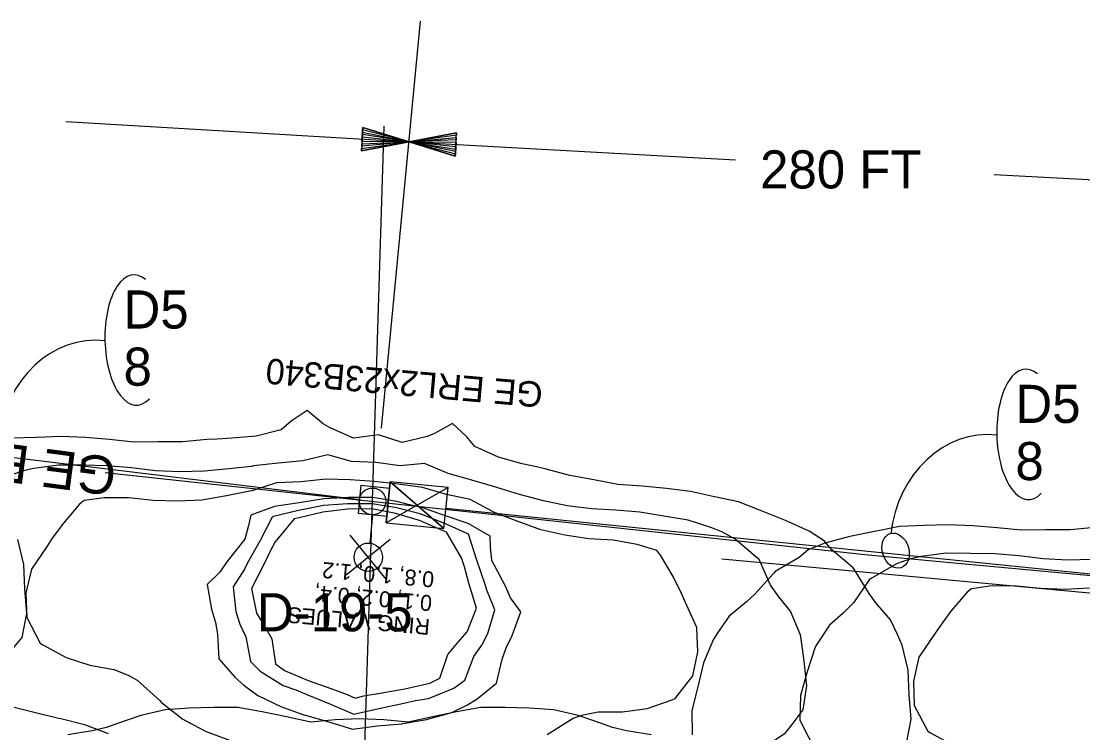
# Model space of a CAD drawing. Extents: x 1638506 to 1658005, y 834807 to 846788.
# Drawn here: x 1642635.4 to 1642969.6, y 842261.9 to 842485.9 of the extents above; entities that cross this region are included whole.
import ezdxf

# ---------------------------------------------------------------- set-up
doc = ezdxf.new("R2010")
doc.units = 0
for name, color, linetype in [('Default', 7, 'Continuous'), ('Exist Guardrail', 7, 'Continuous'), ('Old_Level_1', 7, 'Continuous'), ('Old_Level_2', 7, 'Continuous'), ('Scratch_Level_0', 7, 'Continuous')]:
    doc.layers.add(name, color=color, linetype=linetype)

msp = doc.modelspace()

# ---------------------------------------------------------------- linework, layer by layer
at = {"layer": 'Default'}
for p, q in [((1642756.42, 842436.54), (1642761.14, 842485.89)), ((1642649.53, 842454.33), (1642757.5, 842447.89)), ((1642757.5, 842447.89), (1642860.27, 842442.22)), ((1642941.72, 842437.69), (1643037.67, 842432.39)), ((1642748.87, 842357.77), (1642756.41, 842436.53)), ((1642490.3, 842365.77), (1642742.03, 842335.36)), ((1642768.48, 842326.18), (1642751.59, 842340.91)), ((1642769.78, 842339.08), (1642750.29, 842328.02)), ((1642746.04, 842330.48), (1642745.14, 842321.58)), ((1642769.13, 842332.63), (1643003.18, 842308.79)), ((1642750.36, 842310.22), (1642739.03, 842324.06)), ((1642751.6, 842322.79), (1642737.76, 842311.49)), ((1642744.69, 842317.13), (1642744.69, 842317.13)), ((1642748.18, 842320), (1642748.18, 842320))]:
    msp.add_line(p, q, dxfattribs=at)
for points in [[(1642742.73, 842448.77), (1642742.78, 842449.51), (1642757.5, 842447.89), (1642742.82, 842450.2), (1642742.86, 842450.93), (1642757.5, 842447.89), (1642742.91, 842451.67), (1642742.95, 842452.41), (1642757.5, 842447.89), (1642742.56, 842445.07), (1642742.56, 842445.81), (1642757.5, 842447.89), (1642742.65, 842446.55), (1642742.64, 842447.29), (1642757.5, 842447.89), (1642742.69, 842448.03), (1642742.95, 842452.41), (1642742.56, 842445.07), (1642757.5, 842447.89), (1642742.95, 842452.41)], [(1642772.28, 842447.07), (1642772.24, 842446.33), (1642757.5, 842447.89), (1642772.2, 842445.64), (1642772.16, 842444.91), (1642757.5, 842447.89), (1642772.12, 842444.17), (1642772.08, 842443.43), (1642757.5, 842447.89), (1642772.43, 842450.77), (1642772.44, 842450.03), (1642757.5, 842447.89), (1642772.35, 842449.29), (1642772.36, 842448.55), (1642757.5, 842447.89), (1642772.32, 842447.81), (1642772.08, 842443.43), (1642772.43, 842450.77), (1642757.5, 842447.89), (1642772.08, 842443.43)]]:
    msp.add_lwpolyline(points, dxfattribs=at)
for points in [[(1642769.78, 842339.08), (1642751.59, 842340.91), (1642750.29, 842328.02), (1642768.48, 842326.18)], [(1642760.03, 842333.55), (1642750.29, 842328.02), (1642751.59, 842340.91)], [(1642751.38, 842338.9), (1642750.49, 842330.03), (1642741.59, 842330.93), (1642742.48, 842339.8)], [(1642760.03, 842333.55), (1642768.48, 842326.18), (1642769.78, 842339.08)]]:
    msp.add_lwpolyline(points, close=True, dxfattribs=at)
msp.add_circle((1642744.69, 842317.16), 4.47, dxfattribs=at)
for centre, major_axis, ratio, start_param, end_param in [((1642671.35, 842385.55), (-0.49, 20.52), 0.466223, 5.884886, 7.853982), ((1642658, 842350.99), (-3.78, -34.34), 0.862742, 3.141593, 4.712389), ((1642671.35, 842385.55), (-0.49, 20.52), 0.466223, 1.570796, 3.572354), ((1642952.09, 842355.84), (-0.49, 20.52), 0.466223, 5.884886, 7.853982), ((1642938.74, 842321.27), (-3.78, -34.34), 0.862742, 3.141593, 4.712389), ((1642952.09, 842355.84), (-0.49, 20.52), 0.466223, 1.570796, 3.572354)]:
    msp.add_ellipse(centre, major_axis=major_axis, ratio=ratio, start_param=start_param, end_param=end_param, dxfattribs=at)
msp.add_ellipse((1642910.68, 842319.24), major_axis=(1.72, -5.4), ratio=0.730797, dxfattribs=at)
at = {"layer": 'Exist Guardrail'}
msp.add_lwpolyline([(1642855.97, 842316.64), (1642901.48, 842312.43), (1642956.93, 842307.27), (1643008.14, 842302.6), (1643057.7, 842298.05), (1643110.69, 842293.31), (1643169.76, 842287.95), (1643218.45, 842283.37)], dxfattribs=at)
at = {"layer": 'Old_Level_1'}
for points in [[(1642914.13, 842258.59), (1642915.53, 842266.15), (1642914.97, 842273.87), (1642914.58, 842281.59), (1642912.75, 842289.43), (1642911.29, 842292.79), (1642909.08, 842297.43), (1642904.49, 842302.83), (1642902.38, 842305.69), (1642897.71, 842313.14), (1642897.26, 842313.82), (1642890.59, 842319.52), (1642888.21, 842322.29), (1642883.42, 842325.35), (1642876.04, 842328.71), (1642868.67, 842331.68), (1642868.62, 842331.7), (1642861.19, 842334.59), (1642853.66, 842336.22), (1642846.12, 842337.8), (1642838.53, 842338.8), (1642830.91, 842339.51), (1642823.27, 842340.03), (1642815.73, 842341.53), (1642808.16, 842342.85), (1642800.66, 842344.91), (1642797.58, 842345.58), (1642793.13, 842346.61), (1642785.63, 842348.65), (1642778.24, 842351.97), (1642775.62, 842355.18), (1642771.21, 842359.3), (1642765.57, 842356.06), (1642763.17, 842355.2), (1642755.32, 842353.29), (1642747.85, 842355.64), (1642740.08, 842354.62), (1642732.68, 842357.87), (1642730.46, 842359.13), (1642725.48, 842363.3), (1642720.41, 842360.01), (1642717.28, 842357.3), (1642709.42, 842355.32), (1642701.68, 842354.61), (1642697.12, 842354.37), (1642693.97, 842354.25), (1642686.23, 842353.52), (1642678.55, 842353.53), (1642670.86, 842353.37), (1642663.25, 842354.18), (1642655.62, 842354.8), (1642647.97, 842355.14), (1642640.27, 842354.88), (1642632.57, 842354.59)], [(1642869.82, 842257.66), (1642876.02, 842261.92), (1642878.1, 842264.48), (1642881.53, 842269.12), (1642882.68, 842276.7), (1642881.91, 842284.45), (1642880.87, 842292.22), (1642880.59, 842292.95), (1642877.53, 842300.19), (1642873.93, 842304.65), (1642871.27, 842308.41), (1642867.75, 842316.4), (1642867.32, 842316.8), (1642860.17, 842322.82), (1642856.02, 842325.11), (1642852.8, 842326.41), (1642845.33, 842328.78), (1642837.76, 842330.09), (1642830.19, 842331.31), (1642822.57, 842331.98), (1642814.92, 842332.36), (1642807.33, 842333.33), (1642799.79, 842334.87), (1642792.29, 842336.95), (1642785.49, 842338.96), (1642784.81, 842339.26), (1642777.32, 842341.46), (1642769.82, 842343.48), (1642762.42, 842346.71), (1642754.68, 842345.97), (1642747.09, 842346.93), (1642739.44, 842347.31), (1642731.94, 842349.37), (1642724.1, 842347.48), (1642716.36, 842346.8), (1642708.6, 842345.92), (1642707.88, 842345.75), (1642700.84, 842344.95), (1642693.09, 842344.2), (1642685.4, 842344), (1642677.75, 842344.36), (1642670.15, 842345.32), (1642662.53, 842345.97), (1642654.86, 842346.09), (1642647.18, 842346.12), (1642639.41, 842345.07), (1642636.02, 842344.35), (1642631.54, 842342.83)], [(1642801.03, 842261.36), (1642809.16, 842266.45), (1642812.29, 842267.5), (1642817.01, 842268.47), (1642824.7, 842268.54), (1642832.47, 842269.59), (1642840.38, 842272.25), (1642841.29, 842272.64), (1642846.86, 842279.83), (1642848.45, 842287.37), (1642848.06, 842295.09), (1642844.45, 842303.08), (1642843.32, 842305.78), (1642840.67, 842311.09), (1642836.69, 842317.84), (1642835.47, 842319.23), (1642829.3, 842321.19), (1642821.74, 842322.48), (1642814.11, 842323), (1642806.52, 842324.1), (1642798.99, 842325.81), (1642791.55, 842328.53), (1642784.12, 842331.35), (1642783.99, 842331.41), (1642776.78, 842335.28), (1642769.25, 842336.94), (1642761.76, 842339.08), (1642754.17, 842340.16), (1642746.57, 842340.99), (1642738.93, 842341.49), (1642731.27, 842341.75), (1642723.52, 842340.94), (1642715.82, 842340.61), (1642708.04, 842338.05), (1642707.91, 842338.02), (1642700.1, 842336.53), (1642692.3, 842335.15), (1642684.59, 842334.77), (1642676.93, 842335.01), (1642669.32, 842335.81), (1642661.65, 842335.86), (1642655.23, 842334.99), (1642653.79, 842333.84), (1642648.7, 842327.89), (1642645.17, 842323.12), (1642643.59, 842320.65), (1642638.64, 842313.41), (1642636.92, 842305.88), (1642637.17, 842298.18), (1642641.41, 842290.13)], [(1642695.35, 842300.77), (1642696.61, 842296.65), (1642697.2, 842292.93), (1642697.64, 842285.21), (1642702.77, 842279.29), (1642705.48, 842276.84), (1642709.96, 842273.66), (1642717.32, 842270.05), (1642724.44, 842267.5), (1642724.77, 842267.4), (1642732.27, 842265.39), (1642739.74, 842263.02), (1642747.51, 842264.06), (1642755.25, 842264.74), (1642755.59, 842264.78), (1642763.05, 842266.05), (1642770.93, 842268.32), (1642775.89, 842270.68), (1642778.98, 842272.62), (1642785.06, 842277.56), (1642786.83, 842285.08), (1642788.06, 842288.65), (1642790.02, 842292.48), (1642792.69, 842299.93), (1642789.44, 842304.41), (1642787.88, 842308.03), (1642783.54, 842316.09), (1642783.16, 842320.44), (1642783.01, 842323.81), (1642776.13, 842327.79), (1642768.67, 842330.31), (1642761.22, 842332.89), (1642757.22, 842333.75), (1642753.69, 842334.66), (1642746.13, 842336), (1642738.45, 842335.99), (1642734.82, 842335.71), (1642730.73, 842335.55), (1642722.94, 842334.31), (1642715.16, 842333.13), (1642707.69, 842330.4), (1642706.96, 842327.11), (1642705.83, 842322.89), (1642700.16, 842315.71), (1642697.99, 842312.41), (1642694.01, 842308.56), (1642695.35, 842300.77)], [(1642703.04, 842300.09), (1642704.24, 842296.1), (1642706.12, 842292.15), (1642707.6, 842284.34), (1642710.63, 842281.29), (1642717.91, 842276.73), (1642721.84, 842275.41), (1642725.34, 842273.91), (1642732.75, 842270.86), (1642740.16, 842267.8), (1642747.99, 842269.52), (1642755.82, 842271.24), (1642759.53, 842272.11), (1642763.63, 842272.73), (1642771.59, 842275.95), (1642775.11, 842278.43), (1642777.92, 842285.86), (1642780.45, 842289.44), (1642782.33, 842293.16), (1642784.53, 842300.64), (1642781.97, 842306.75), (1642781.43, 842308.59), (1642778.72, 842316.51), (1642776.25, 842324.41), (1642775.85, 842324.64), (1642768.46, 842327.9), (1642761.03, 842330.8), (1642753.52, 842332.69), (1642745.95, 842333.95), (1642738.28, 842334.02), (1642730.55, 842333.47), (1642722.73, 842331.9), (1642714.88, 842329.97), (1642714.45, 842329.81), (1642710.64, 842322.47), (1642706.61, 842315.14), (1642705.76, 842313.41), (1642702.17, 842307.85), (1642703.04, 842300.09)], [(1642709.52, 842299.53), (1642711.88, 842295.66), (1642714.3, 842291.43), (1642715.46, 842283.65), (1642718.32, 842281.47), (1642725.73, 842278.36), (1642733.17, 842275.7), (1642738.06, 842273.99), (1642740.6, 842272.82), (1642743.31, 842273.53), (1642748.42, 842274.37), (1642756.21, 842275.69), (1642764.05, 842277.47), (1642767.24, 842279.12), (1642769.73, 842286.58), (1642772.85, 842290.32), (1642775.85, 842293.72), (1642778.75, 842301.15), (1642776.37, 842309.04), (1642774.94, 842314.16), (1642773.99, 842316.92), (1642769.33, 842325.01), (1642768.25, 842325.5), (1642760.85, 842328.72), (1642753.36, 842330.93), (1642745.81, 842332.37), (1642738.12, 842332.26), (1642730.37, 842331.39), (1642722.52, 842329.5), (1642721.38, 842329.21), (1642715.38, 842322.05), (1642713.97, 842319.5), (1642711.66, 842314.7), (1642707.95, 842307.34), (1642709.52, 842299.53)], [(1642973.33, 842326.51), (1642965.59, 842325.78), (1642957.91, 842325.8), (1642950.22, 842325.63), (1642942.61, 842326.45), (1642934.99, 842327.07), (1642927.34, 842327.4), (1642919.64, 842327.15), (1642911.93, 842326.86), (1642904.12, 842325.3), (1642904.06, 842325.29), (1642896.29, 842323.65), (1642888.43, 842321.62), (1642883.19, 842319.44), (1642880.36, 842317.12), (1642872.8, 842312.67), (1642872.24, 842312.08), (1642866.36, 842305.55), (1642863.78, 842303.1), (1642858.32, 842298.58), (1642855.34, 842294.39), (1642853.32, 842291.33), (1642850.16, 842283.93), (1642848.43, 842276.4), (1642846.54, 842268.89), (1642846.61, 842261.2)], [(1642629.71, 842284.76), (1642635.76, 842291.91), (1642637.16, 842299.47), (1642636.61, 842307.2), (1642636.21, 842314.91), (1642634.39, 842322.75)], [(1642972.46, 842316.47), (1642964.76, 842316.26), (1642957.11, 842316.62), (1642949.52, 842317.59), (1642941.89, 842318.24), (1642934.22, 842318.36), (1642926.55, 842318.39), (1642918.78, 842317.34), (1642915.38, 842316.62), (1642910.9, 842315.09), (1642902.81, 842310.4), (1642902.32, 842310.08), (1642897.46, 842302.83), (1642894.19, 842299.58), (1642889.87, 842295.82), (1642885.6, 842289.22), (1642885.19, 842288.54), (1642882.82, 842281.07), (1642880.72, 842273.58), (1642880.53, 842265.91)], [(1642971.66, 842307.42), (1642963.95, 842307.04), (1642956.29, 842307.27), (1642948.68, 842308.08), (1642941.01, 842308.12), (1642934.6, 842307.26), (1642933.15, 842306.11), (1642928.06, 842300.15), (1642924.54, 842295.39), (1642922.95, 842292.92), (1642918.01, 842285.67), (1642916.28, 842278.15), (1642916.54, 842270.44), (1642920.78, 842262.39)], [(1642641.41, 842290.13), (1642642.24, 842289.58), (1642649.57, 842285.6), (1642657.04, 842283.21), (1642664.6, 842281.8), (1642669.08, 842280.03), (1642671.98, 842278.45), (1642679.1, 842272.03), (1642679.57, 842271.43), (1642686.27, 842266.19), (1642693.05, 842262.57), (1642693.61, 842262.35), (1642701.05, 842259.57)], [(1642632.85, 842270.03), (1642640.36, 842268.15), (1642646.8, 842266.62), (1642647.88, 842266.34), (1642655.4, 842264.5), (1642662.83, 842261.66)], [(1642833.7, 842261.23), (1642826.05, 842262.46), (1642821.55, 842263.6), (1642818.4, 842264.75), (1642810.75, 842267.35), (1642803.1, 842269.11), (1642795.45, 842269.65), (1642787.8, 842269.88), (1642780.15, 842269.88), (1642772.5, 842268.49), (1642764.85, 842266.91), (1642757.2, 842265.19), (1642749.55, 842265.94), (1642741.9, 842266.24), (1642734.25, 842265.94), (1642726.6, 842265.19), (1642718.95, 842266.91), (1642711.3, 842268.49), (1642703.65, 842269.88), (1642696, 842269.88), (1642688.35, 842269.65), (1642680.7, 842269.11), (1642673.05, 842267.35), (1642665.4, 842264.75), (1642662.25, 842263.6), (1642657.75, 842262.46), (1642650.1, 842261.23)], [(1642880.53, 842265.91), (1642883.11, 842260.75), (1642884.72, 842257.87), (1642890.07, 842252.59), (1642896.21, 842249.18), (1642897.41, 842248.66), (1642904.8, 842245.4), (1642912.21, 842242.3), (1642919.73, 842240.41), (1642926.16, 842238.89), (1642927.25, 842238.6), (1642934.77, 842236.77), (1642942.2, 842233.93), (1642949.6, 842230.8), (1642955.37, 842228.65), (1642957.03, 842227.91), (1642964.43, 842224.72), (1642971.99, 842223.38)], [(1642920.78, 842262.39), (1642921.6, 842261.85), (1642928.93, 842257.86), (1642936.4, 842255.48), (1642943.96, 842254.07), (1642948.44, 842252.29), (1642951.34, 842250.71), (1642958.46, 842244.29), (1642958.94, 842243.7), (1642965.63, 842238.46), (1642972.41, 842234.84)]]:
    msp.add_lwpolyline(points, dxfattribs=at)
msp.add_circle((1642746.02, 842334.73), 4.21, dxfattribs=at)
at = {"layer": 'Old_Level_2'}
msp.add_line((1642738.69, 842099.7), (1642749.71, 842452.88), dxfattribs=at)
msp.add_lwpolyline([(1642661.86, 842343.82), (1642901.99, 842317.91), (1642957.43, 842312.75), (1643008.64, 842308.08), (1643058.2, 842303.53), (1643111.19, 842298.79), (1643170.27, 842293.42), (1643218.96, 842288.85)], dxfattribs=at)

# ---------------------------------------------------------------- texts
at = {"layer": 'Default'}
for s, p in [('280 FT', (1642868.01, 842433.24)), ('D5', (1642667.64, 842389.15)), ('8', (1642667.64, 842371.15)), ('D5', (1642948.38, 842359.43)), ('8', (1642948.38, 842341.43)), ('D-19-5', (1642709.62, 842293.84))]:
    msp.add_text(s, height=12, dxfattribs=at).set_placement(p)
at = {"layer": 'Old_Level_1'}
for s, height, p in [('GE ERL2x23B340', 8, (1642799.9, 842372.2)), ('0.8, 1.0, 1.2', 5, (1642765.59, 842312.59)), ('0.1, 0.2, 0.4,', 5, (1642764.93, 842305.12)), ('RING VALUES', 5, (1642764.28, 842297.64))]:
    msp.add_text(s, height=height, rotation=175, dxfattribs=at).set_placement(p)
at = {"layer": 'Scratch_Level_0'}
msp.add_text('GE ERL2x23C340', height=12, rotation=172.4934, dxfattribs=at).set_placement((1642665.94, 842348.34))

doc.saveas('drawing.dxf')
